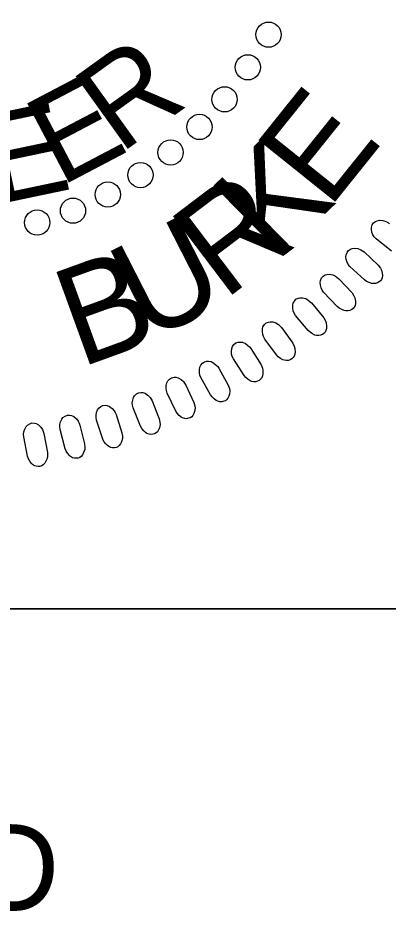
# Model space of a CAD drawing. Extents: x 502400 to 509344, y 448070 to 484209.
# Drawn here: x 507224.6 to 507248.1, y 484026.9 to 484083.6 of the extents above; entities that cross this region are included whole.
import ezdxf

# ---------------------------------------------------------------- set-up
doc = ezdxf.new("R2010")
doc.units = 0
for name, color, linetype in [('Sheet PE Seal Cell', 7, 'Continuous'), ('Sheet Profile CELL', 7, 'Continuous'), ('Sheet Sticker Exception Certification CELL', 7, 'Continuous')]:
    doc.layers.add(name, color=color, linetype=linetype)

msp = doc.modelspace()

# ---------------------------------------------------------------- linework, layer by layer
at = {"layer": 'Sheet PE Seal Cell'}
msp.add_lwpolyline([(507248.314, 484068.847), (507247.341, 484069.643), (507247.225, 484069.768), (507247.146, 484069.892), (507247.08, 484070.062), (507247.044, 484070.238), (507247.045, 484070.364), (507247.098, 484070.523), (507247.179, 484070.651), (507247.305, 484070.74), (507247.41, 484070.789), (507247.567, 484070.824), (507247.774, 484070.808), (507247.956, 484070.745), (507248.074, 484070.685), (507248.184, 484070.614)], dxfattribs=at)
for points in [[(507246.59, 484068.803), (507247.483, 484067.963), (507247.618, 484067.785), (507247.684, 484067.652), (507247.731, 484067.453), (507247.744, 484067.308), (507247.725, 484067.171), (507247.683, 484067.068), (507247.62, 484066.973), (507247.529, 484066.904), (507247.425, 484066.838), (507247.311, 484066.802), (507247.166, 484066.795), (507247.067, 484066.806), (507246.911, 484066.859), (507246.74, 484066.938), (507246.608, 484067.031), (507245.687, 484067.886), (507245.579, 484068.019), (507245.508, 484068.148), (507245.453, 484068.322), (507245.428, 484068.498), (507245.437, 484068.625), (507245.5, 484068.78), (507245.589, 484068.902), (507245.72, 484068.984), (507245.828, 484069.026), (507245.988, 484069.051), (507246.193, 484069.021), (507246.37, 484068.948), (507246.485, 484068.881)], [(507244.977, 484067.109), (507245.817, 484066.214), (507245.94, 484066.029), (507245.998, 484065.891), (507246.032, 484065.691), (507246.036, 484065.544), (507246.008, 484065.409), (507245.96, 484065.309), (507245.891, 484065.217), (507245.796, 484065.155), (507245.688, 484065.095), (507245.572, 484065.067), (507245.426, 484065.068), (507245.328, 484065.086), (507245.177, 484065.149), (507245.01, 484065.239), (507244.885, 484065.34), (507244.019, 484066.251), (507243.92, 484066.39), (507243.857, 484066.523), (507243.813, 484066.7), (507243.799, 484066.878), (507243.816, 484067.003), (507243.889, 484067.155), (507243.985, 484067.271), (507244.121, 484067.344), (507244.231, 484067.379), (507244.392, 484067.394), (507244.595, 484067.352), (507244.768, 484067.267), (507244.878, 484067.193)], [(507243.245, 484065.58), (507244.027, 484064.634), (507244.138, 484064.441), (507244.186, 484064.3), (507244.208, 484064.098), (507244.203, 484063.952), (507244.167, 484063.818), (507244.112, 484063.721), (507244.039, 484063.634), (507243.94, 484063.579), (507243.828, 484063.526), (507243.71, 484063.505), (507243.565, 484063.515), (507243.468, 484063.538), (507243.321, 484063.611), (507243.16, 484063.712), (507243.042, 484063.82), (507242.235, 484064.783), (507242.145, 484064.928), (507242.09, 484065.065), (507242.058, 484065.245), (507242.055, 484065.423), (507242.079, 484065.547), (507242.162, 484065.693), (507242.264, 484065.804), (507242.405, 484065.868), (507242.518, 484065.897), (507242.679, 484065.901), (507242.879, 484065.846), (507243.046, 484065.751), (507243.151, 484065.67)], [(507241.339, 484064.014), (507242.059, 484063.021), (507242.158, 484062.822), (507242.198, 484062.679), (507242.207, 484062.475), (507242.192, 484062.329), (507242.149, 484062.198), (507242.087, 484062.105), (507242.008, 484062.023), (507241.906, 484061.974), (507241.792, 484061.928), (507241.672, 484061.914), (507241.528, 484061.934), (507241.433, 484061.963), (507241.29, 484062.044), (507241.137, 484062.155), (507241.025, 484062.27), (507240.28, 484063.282), (507240.199, 484063.433), (507240.154, 484063.573), (507240.132, 484063.754), (507240.141, 484063.933), (507240.173, 484064.055), (507240.264, 484064.196), (507240.374, 484064.3), (507240.519, 484064.355), (507240.632, 484064.376), (507240.794, 484064.37), (507240.99, 484064.304), (507241.151, 484064.197), (507241.25, 484064.11)], [(507239.395, 484062.686), (507240.052, 484061.649), (507240.138, 484061.445), (507240.168, 484061.298), (507240.164, 484061.095), (507240.141, 484060.95), (507240.089, 484060.823), (507240.023, 484060.733), (507239.938, 484060.656), (507239.833, 484060.613), (507239.716, 484060.574), (507239.595, 484060.569), (507239.454, 484060.597), (507239.36, 484060.632), (507239.223, 484060.722), (507239.076, 484060.842), (507238.972, 484060.964), (507238.293, 484062.022), (507238.221, 484062.177), (507238.185, 484062.319), (507238.175, 484062.502), (507238.194, 484062.68), (507238.234, 484062.799), (507238.334, 484062.934), (507238.45, 484063.031), (507238.598, 484063.078), (507238.713, 484063.091), (507238.873, 484063.076), (507239.065, 484062.996), (507239.219, 484062.88), (507239.313, 484062.787)], [(507237.376, 484061.43), (507237.966, 484060.354), (507238.039, 484060.144), (507238.061, 484059.996), (507238.044, 484059.794), (507238.012, 484059.651), (507237.952, 484059.527), (507237.879, 484059.442), (507237.79, 484059.37), (507237.683, 484059.334), (507237.564, 484059.303), (507237.443, 484059.304), (507237.304, 484059.342), (507237.213, 484059.383), (507237.081, 484059.482), (507236.943, 484059.61), (507236.846, 484059.739), (507236.235, 484060.837), (507236.173, 484060.996), (507236.145, 484061.141), (507236.147, 484061.323), (507236.177, 484061.499), (507236.224, 484061.616), (507236.333, 484061.744), (507236.455, 484061.834), (507236.605, 484061.87), (507236.721, 484061.877), (507236.88, 484061.852), (507237.066, 484061.76), (507237.212, 484061.635), (507237.3, 484061.536)], [(507235.274, 484060.366), (507235.796, 484059.256), (507235.855, 484059.042), (507235.868, 484058.893), (507235.839, 484058.692), (507235.797, 484058.551), (507235.729, 484058.431), (507235.652, 484058.35), (507235.558, 484058.285), (507235.449, 484058.256), (507235.328, 484058.232), (507235.208, 484058.24), (507235.071, 484058.287), (507234.982, 484058.333), (507234.858, 484058.44), (507234.728, 484058.577), (507234.639, 484058.712), (507234.098, 484059.846), (507234.046, 484060.009), (507234.027, 484060.155), (507234.041, 484060.337), (507234.083, 484060.511), (507234.137, 484060.625), (507234.253, 484060.746), (507234.38, 484060.827), (507234.532, 484060.855), (507234.648, 484060.854), (507234.805, 484060.818), (507234.986, 484060.716), (507235.124, 484060.581), (507235.205, 484060.477)], [(507233.146, 484059.359), (507233.597, 484058.218), (507233.643, 484058), (507233.646, 484057.852), (507233.604, 484057.652), (507233.554, 484057.515), (507233.479, 484057.399), (507233.397, 484057.324), (507233.299, 484057.264), (507233.188, 484057.242), (507233.066, 484057.225), (507232.946, 484057.242), (507232.813, 484057.297), (507232.727, 484057.349), (507232.61, 484057.463), (507232.489, 484057.608), (507232.409, 484057.748), (507231.94, 484058.914), (507231.898, 484059.08), (507231.889, 484059.226), (507231.913, 484059.407), (507231.966, 484059.578), (507232.027, 484059.689), (507232.15, 484059.802), (507232.283, 484059.876), (507232.436, 484059.894), (507232.553, 484059.885), (507232.707, 484059.839), (507232.88, 484059.726), (507233.01, 484059.584), (507233.084, 484059.474)], [(507230.854, 484058.5), (507231.232, 484057.333), (507231.265, 484057.113), (507231.258, 484056.964), (507231.204, 484056.768), (507231.145, 484056.634), (507231.063, 484056.523), (507230.976, 484056.453), (507230.875, 484056.4), (507230.763, 484056.384), (507230.64, 484056.376), (507230.522, 484056.4), (507230.392, 484056.463), (507230.31, 484056.52), (507230.2, 484056.642), (507230.087, 484056.794), (507230.017, 484056.939), (507229.622, 484058.132), (507229.591, 484058.3), (507229.591, 484058.446), (507229.626, 484058.626), (507229.69, 484058.793), (507229.758, 484058.899), (507229.889, 484059.005), (507230.025, 484059.07), (507230.179, 484059.078), (507230.294, 484059.062), (507230.446, 484059.008), (507230.611, 484058.883), (507230.731, 484058.732), (507230.8, 484058.619)], [(507228.562, 484057.829), (507228.867, 484056.64), (507228.885, 484056.419), (507228.869, 484056.27), (507228.803, 484056.078), (507228.736, 484055.948), (507228.647, 484055.842), (507228.556, 484055.778), (507228.451, 484055.731), (507228.339, 484055.722), (507228.215, 484055.722), (507228.099, 484055.753), (507227.972, 484055.824), (507227.895, 484055.886), (507227.792, 484056.015), (507227.69, 484056.174), (507227.629, 484056.323), (507227.309, 484057.538), (507227.289, 484057.708), (507227.298, 484057.854), (507227.345, 484058.031), (507227.419, 484058.194), (507227.493, 484058.296), (507227.63, 484058.393), (507227.771, 484058.449), (507227.925, 484058.447), (507228.039, 484058.425), (507228.187, 484058.361), (507228.344, 484058.225), (507228.455, 484058.068), (507228.516, 484057.951)], [(507226.276, 484057.291), (507226.505, 484056.085), (507226.51, 484055.863), (507226.485, 484055.716), (507226.407, 484055.528), (507226.331, 484055.403), (507226.236, 484055.303), (507226.141, 484055.244), (507226.034, 484055.204), (507225.921, 484055.203), (507225.798, 484055.21), (507225.683, 484055.249), (507225.562, 484055.327), (507225.488, 484055.394), (507225.394, 484055.529), (507225.302, 484055.694), (507225.25, 484055.846), (507225.008, 484057.079), (507224.998, 484057.25), (507225.016, 484057.396), (507225.074, 484057.569), (507225.158, 484057.727), (507225.239, 484057.824), (507225.381, 484057.912), (507225.525, 484057.96), (507225.679, 484057.948), (507225.791, 484057.919), (507225.935, 484057.845), (507226.084, 484057.701), (507226.184, 484057.536), (507226.237, 484057.415)]]:
    msp.add_lwpolyline(points, close=True, dxfattribs=at)
for centre in [(507240.526, 484082.586), (507239.212, 484080.515), (507237.738, 484078.484), (507236.145, 484076.732), (507234.316, 484075.116), (507232.404, 484073.682), (507230.334, 484072.448), (507228.127, 484071.425), (507225.857, 484070.669)]:
    msp.add_circle(centre, 0.801, dxfattribs=at)
at = {"layer": 'Sheet Profile CELL'}
msp.add_lwpolyline([(507169.08, 484158.662), (507269.08, 484158.662), (507269.08, 484046.162), (507169.08, 484046.162)], close=True, dxfattribs=at)
at = {"layer": 'Sheet Sticker Exception Certification CELL'}
msp.add_line((507069.03, 484046.162), (507269.067, 484046.162), dxfattribs=at)
msp.add_line((507069.03, 484046.162), (507269.067, 484046.162), dxfattribs=at)

# ---------------------------------------------------------------- texts
at = {"layer": 'Sheet PE Seal Cell'}
for s, height, rotation, p in [('R', 5.669, 35.6636, (507231.094, 484074.979)), ('E', 5.669, 27.7238, (507227.313, 484072.917)), ('E', 6.236, 51.2683, (507244.323, 484071.453)), ('E', 5.669, 11.8442, (507223.243, 484071.794)), ('K', 6.236, 44.4226, (507240.918, 484068.079)), ('R', 6.236, 37.1476, (507237.687, 484065.686)), ('U', 6.236, 27.0477, (507232.783, 484063.019)), ('B', 6.236, 19.9309, (507228.563, 484061.437))]:
    msp.add_text(s, height=height, rotation=rotation, dxfattribs=at).set_placement(p)
at = {"layer": 'Sheet Sticker Exception Certification CELL'}
msp.add_text('UNLESS ALL SIGNATURES COMPLETED', height=5.5, dxfattribs=at).set_placement((507085.03, 484027.016))
msp.add_text('UNLESS ALL SIGNATURES COMPLETED', height=5.5, dxfattribs=at).set_placement((507085.03, 484027.016))

doc.saveas('drawing.dxf')
